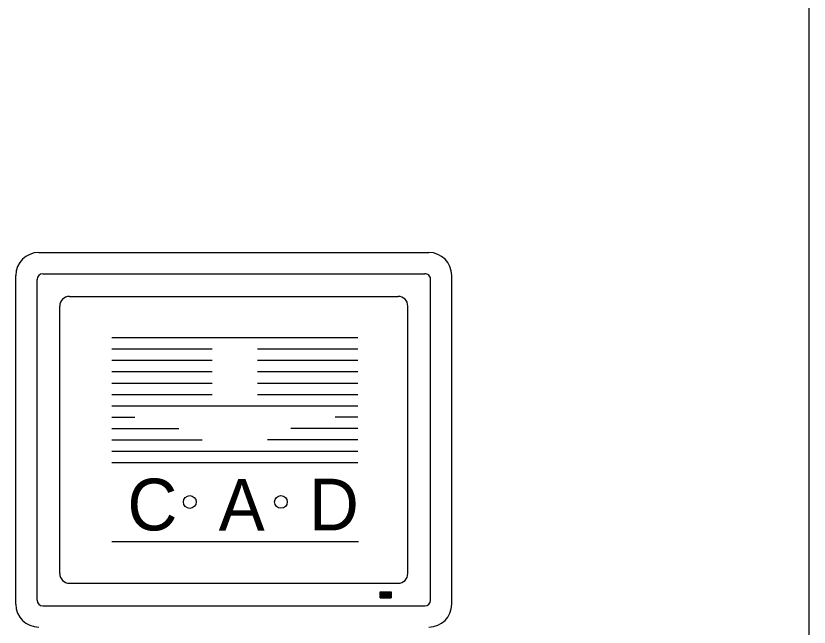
# Model space of a CAD drawing. Extents: x 22339.2 to 22413.4, y 22369.6 to 22418.8.
# Drawn here: x 22406.007 to 22409.05, y 22372.361 to 22374.705 of the extents above; entities that cross this region are included whole.
import ezdxf

# ---------------------------------------------------------------- set-up
doc = ezdxf.new("R2010")
doc.units = 0
for name, color, linetype in [('Level 2', 7, 'Continuous'), ('Level 3', 7, 'Continuous'), ('Level 5', 7, 'Continuous'), ('Level 9', 7, 'Continuous')]:
    doc.layers.add(name, color=color, linetype=linetype)

msp = doc.modelspace()

# ---------------------------------------------------------------- linework, layer by layer
at = {"layer": 'Level 2'}
for p, q in [((22406.2125, 22373.6292), (22407.4741, 22373.6292)), ((22406.1758, 22372.566), (22406.1758, 22373.5925)), ((22407.5108, 22372.566), (22407.5108, 22373.5925)), ((22406.2125, 22372.5293), (22407.4741, 22372.5293)), ((22407.405, 22372.4948), (22407.4468, 22372.4948)), ((22407.405, 22372.4937), (22407.4468, 22372.4937)), ((22407.405, 22372.4923), (22407.4468, 22372.4923)), ((22407.405, 22372.4908), (22407.4468, 22372.4908)), ((22407.405, 22372.4895), (22407.4468, 22372.4895)), ((22407.405, 22372.4883), (22407.4468, 22372.4883)), ((22407.405, 22372.487), (22407.4468, 22372.487)), ((22407.405, 22372.4857), (22407.4468, 22372.4857)), ((22407.405, 22372.4843), (22407.4468, 22372.4843)), ((22407.405, 22372.483), (22407.4468, 22372.483)), ((22407.405, 22372.4817), (22407.4468, 22372.4817)), ((22407.405, 22372.4803), (22407.4468, 22372.4803)), ((22407.405, 22372.4792), (22407.4468, 22372.4792)), ((22407.405, 22372.4777), (22407.4468, 22372.4777)), ((22407.405, 22372.4763), (22407.4468, 22372.4763)), ((22407.405, 22372.4752), (22407.4468, 22372.4752)), ((22407.405, 22372.4738), (22407.4468, 22372.4738))]:
    msp.add_line(p, q, dxfattribs=at)
msp.add_lwpolyline([(22407.405, 22372.4958), (22407.4468, 22372.4958), (22407.4468, 22372.4727), (22407.405, 22372.4727)], close=True, dxfattribs=at)
for centre in [(22406.6745, 22372.8408), (22407.0241, 22372.8409)]:
    msp.add_circle(centre, 0.0244, dxfattribs=at)
for centre, start, end in [((22406.2124, 22373.5925), 90, 180), ((22407.4741, 22373.5925), 0, 90), ((22406.2124, 22372.566), 180, 270), ((22407.4741, 22372.566), 270, 0)]:
    msp.add_arc(centre, 0.0367, start, end, dxfattribs=at)
at = {"layer": 'Level 3'}
for p, q in [((22406.0953, 22373.7977), (22407.5913, 22373.7977)), ((22406.0073, 22372.4488), (22406.0073, 22373.7097)), ((22406.1105, 22373.7165), (22407.5746, 22373.7165)), ((22407.6793, 22372.4488), (22407.6793, 22373.7097)), ((22406.0885, 22372.4642), (22406.0885, 22373.6945)), ((22407.5981, 22372.4642), (22407.5981, 22373.6945)), ((22406.1105, 22372.4422), (22407.5746, 22372.4422))]:
    msp.add_line(p, q, dxfattribs=at)
for centre, radius, start, end in [((22406.0952, 22373.7096), 0.088, 90, 180), ((22407.5912, 22373.7096), 0.088, 0, 90), ((22406.1104, 22373.6945), 0.022, 90, 180), ((22407.5761, 22373.6945), 0.022, 0, 93.8704), ((22406.1104, 22372.464), 0.022, 180, 270), ((22407.5761, 22372.464), 0.022, 270, 0), ((22406.0952, 22372.4489), 0.088, 180, 270), ((22407.5912, 22372.4489), 0.088, 270, 0)]:
    msp.add_arc(centre, radius, start, end, dxfattribs=at)
at = {"layer": 'Level 5'}
for p, q in [((22406.376, 22373.4713), (22407.3193, 22373.4713)), ((22406.376, 22373.4277), (22406.7605, 22373.4277)), ((22406.9346, 22373.4277), (22407.3193, 22373.4277)), ((22406.376, 22373.3842), (22406.7605, 22373.3842)), ((22406.9346, 22373.3842), (22407.3193, 22373.3842)), ((22406.376, 22373.3407), (22406.7605, 22373.3407)), ((22406.9346, 22373.3407), (22407.3193, 22373.3407)), ((22406.376, 22373.297), (22406.7605, 22373.297)), ((22406.9346, 22373.297), (22407.3193, 22373.297)), ((22406.376, 22373.2533), (22406.7605, 22373.2533)), ((22406.9346, 22373.2533), (22407.3193, 22373.2533)), ((22406.376, 22373.2097), (22407.3193, 22373.2097)), ((22406.376, 22373.1663), (22406.4631, 22373.1663)), ((22407.3191, 22373.1663), (22407.232, 22373.1663)), ((22406.376, 22373.1227), (22406.633, 22373.1227)), ((22407.3191, 22373.1227), (22407.0621, 22373.1227)), ((22406.376, 22373.0792), (22406.7223, 22373.0792)), ((22407.3191, 22373.0792), (22406.9728, 22373.0792)), ((22406.376, 22373.0355), (22407.3193, 22373.0355)), ((22406.376, 22372.9918), (22407.3193, 22372.9918)), ((22406.376, 22372.6893), (22407.321, 22372.6893))]:
    msp.add_line(p, q, dxfattribs=at)
at = {"layer": 'Level 9'}
msp.add_lwpolyline([(22409.0502, 22370.2933), (22409.0502, 22414.2933)], dxfattribs=at)

# ---------------------------------------------------------------- texts
at = {"layer": 'Level 5'}
for s, p in [('C', (22406.4351, 22372.7318)), ('A', (22406.7851, 22372.7302)), ('D', (22407.1315, 22372.7318))]:
    msp.add_text(s, height=0.1984, dxfattribs=at).set_placement(p)

doc.saveas('drawing.dxf')
